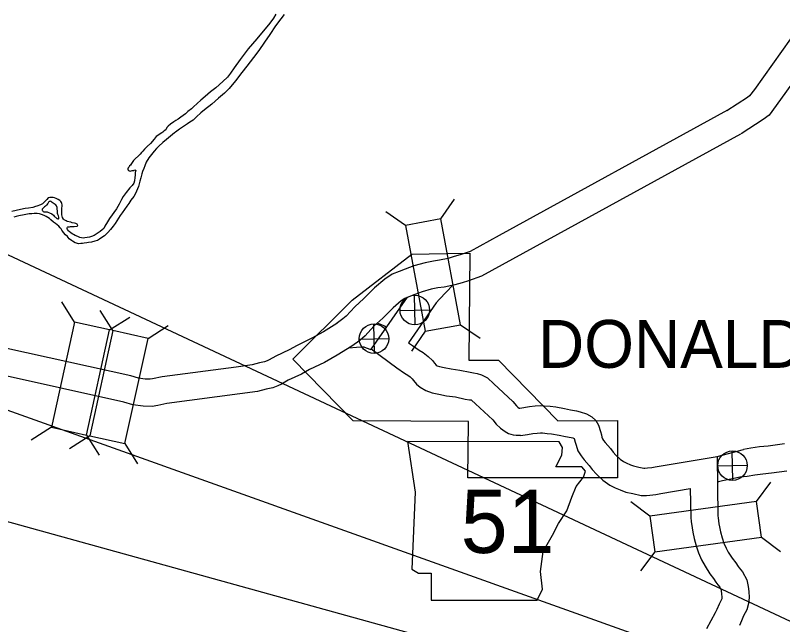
# Model space of a CAD drawing. Extents: x 1373862 to 1377080, y 1164775 to 1170415.
# Drawn here: x 1374487.3 to 1374572, y 1170030.2 to 1170097.4 of the extents above; entities that cross this region are included whole.
import ezdxf

# ---------------------------------------------------------------- set-up
doc = ezdxf.new("R2010")
doc.units = 0
doc.layers.add('1', color=7, linetype='Continuous')
doc.layers.add('Default', color=7, linetype='Continuous')

msp = doc.modelspace()

# ---------------------------------------------------------------- linework, layer by layer
at = {"layer": '1'}
for p in [(1374155.089, 1170226.036), (1374172.843, 1170165.768), (1374199.554, 1170121.066)]:
    msp.add_line(p, (1374640.758, 1169998.763), dxfattribs=at)
at = {"layer": 'Default'}
for p, q in [((1374534.295, 1170074.917), (1374535.789, 1170077.093)), ((1374530.401, 1170074.194), (1374528.225, 1170075.688)), ((1374531.457, 1170063.225), (1374531.382, 1170066.48)), ((1374493.871, 1170063.524), (1374492.452, 1170065.75)), ((1374498.109, 1170062.586), (1374496.689, 1170064.812)), ((1374529.793, 1170064.815), (1374533.047, 1170064.89)), ((1374497.738, 1170062.668), (1374499.964, 1170064.088)), ((1374526.958, 1170060.066), (1374526.883, 1170063.321)), ((1374501.975, 1170061.731), (1374504.201, 1170063.151)), ((1374532.57, 1170062.514), (1374531.076, 1170060.337)), ((1374536.464, 1170063.237), (1374538.64, 1170061.742)), ((1374525.293, 1170061.656), (1374528.548, 1170061.731)), ((1374491.306, 1170051.924), (1374489.08, 1170050.504)), ((1374495.543, 1170050.987), (1374493.317, 1170049.567)), ((1374495.172, 1170051.069), (1374496.592, 1170048.843)), ((1374499.41, 1170050.131), (1374500.829, 1170047.906)), ((1374566.521, 1170046.074), (1374566.446, 1170049.329)), ((1374564.856, 1170047.664), (1374568.111, 1170047.739)), ((1374569.134, 1170043.75), (1374570.726, 1170045.857)), ((1374557.368, 1170042.113), (1374555.262, 1170043.705)), ((1374569.68, 1170039.828), (1374571.786, 1170038.237)), ((1374557.914, 1170038.191), (1374556.322, 1170036.085))]:
    msp.add_line(p, q, dxfattribs=at)
for points in [[(1374516.087, 1170097.466), (1374515.821, 1170097.033), (1374515.406, 1170096.479), (1374513.983, 1170094.764), (1374513.043, 1170093.675), (1374512.134, 1170092.475), (1374511.503, 1170091.558), (1374511.069, 1170090.964), (1374510.743, 1170090.52), (1374510.247, 1170090.075), (1374509.464, 1170089.368), (1374508.869, 1170088.932), (1374508.284, 1170088.416), (1374507.818, 1170087.992), (1374506.996, 1170087.254), (1374506.758, 1170087.031), (1374506.361, 1170086.737), (1374506.123, 1170086.505), (1374505.865, 1170086.303), (1374505.597, 1170086.13), (1374505.309, 1170085.917), (1374505.031, 1170085.755), (1374504.833, 1170085.623), (1374504.445, 1170085.359), (1374504.208, 1170085.137), (1374504.069, 1170084.985), (1374503.931, 1170084.744), (1374503.773, 1170084.632), (1374503.604, 1170084.481), (1374503.495, 1170084.4)], [(1374516.996, 1170097.454), (1374516.62, 1170096.98), (1374516.058, 1170096.184), (1374515.406, 1170095.247), (1374514.834, 1170094.401), (1374514.203, 1170093.474), (1374513.62, 1170092.708), (1374512.889, 1170091.75), (1374512.326, 1170091.045), (1374511.644, 1170090.137), (1374510.933, 1170089.3), (1374510.428, 1170088.785), (1374509.753, 1170088.219), (1374509.03, 1170087.551), (1374508.196, 1170086.933), (1374507.8, 1170086.62), (1374507.314, 1170086.165), (1374506.948, 1170085.811), (1374506.6, 1170085.558), (1374506.352, 1170085.375), (1374505.766, 1170085.01), (1374505.458, 1170084.797), (1374505.141, 1170084.584), (1374504.992, 1170084.472), (1374504.913, 1170084.402)], [(1374573.9, 1170096.142), (1374568.908, 1170089.177), (1374568.375, 1170088.479), (1374568.147, 1170088.299), (1374565.848, 1170086.837)], [(1374576.338, 1170094.394), (1374571.32, 1170087.393), (1374570.53, 1170086.357), (1374569.885, 1170085.849), (1374567.457, 1170084.305)], [(1374565.932, 1170086.887), (1374540.744, 1170073.094), (1374537.549, 1170071.328)], [(1374504.913, 1170084.402), (1374504.01, 1170083.677), (1374503.617, 1170083.348), (1374503.166, 1170082.919), (1374502.912, 1170082.654), (1374502.658, 1170082.358), (1374502.356, 1170082.002), (1374502.083, 1170081.656), (1374501.774, 1170081.149), (1374501.622, 1170080.766), (1374501.499, 1170080.453), (1374501.385, 1170080.141), (1374501.301, 1170079.859), (1374501.17, 1170079.435), (1374501.068, 1170079.053), (1374501.013, 1170078.772), (1374500.929, 1170078.48), (1374500.815, 1170078.207), (1374500.585, 1170077.712), (1374500.393, 1170077.368), (1374500.081, 1170076.961), (1374499.849, 1170076.596), (1374499.645, 1170076.302), (1374499.363, 1170075.936), (1374499.111, 1170075.58), (1374498.907, 1170075.296), (1374498.703, 1170075.001), (1374498.366, 1170074.394), (1374498.142, 1170074.089), (1374497.84, 1170073.743), (1374497.537, 1170073.406), (1374497.371, 1170073.223), (1374497.175, 1170073.039), (1374496.88, 1170072.843), (1374496.624, 1170072.657), (1374496.387, 1170072.533), (1374496.089, 1170072.447), (1374495.751, 1170072.35), (1374495.423, 1170072.303), (1374495.214, 1170072.269), (1374494.945, 1170072.234), (1374494.756, 1170072.21), (1374494.567, 1170072.176), (1374494.347, 1170072.172), (1374493.926, 1170072.283), (1374493.643, 1170072.448), (1374493.542, 1170072.506), (1374493.288, 1170072.701), (1374493.155, 1170072.869), (1374493.074, 1170072.957), (1374492.86, 1170073.163), (1374492.656, 1170073.389), (1374492.573, 1170073.508), (1374492.47, 1170073.666), (1374492.388, 1170073.794), (1374492.265, 1170073.932), (1374492.122, 1170074.089), (1374491.94, 1170074.246), (1374491.767, 1170074.393), (1374491.544, 1170074.548), (1374491.249, 1170074.813), (1374491.087, 1170074.95), (1374490.925, 1170075.057), (1374490.733, 1170075.173), (1374490.501, 1170075.288), (1374490.209, 1170075.403), (1374489.998, 1170075.459), (1374489.748, 1170075.494), (1374489.398, 1170075.507), (1374489.169, 1170075.482), (1374488.86, 1170075.466), (1374488.323, 1170075.365), (1374487.706, 1170075.253), (1374487.418, 1170075.177), (1374487.151, 1170075.081)], [(1374503.495, 1170084.4), (1374502.885, 1170083.995), (1374502.642, 1170083.689), (1374502.251, 1170083.231), (1374501.899, 1170082.874), (1374501.605, 1170082.598), (1374501.41, 1170082.373), (1374501.254, 1170082.21), (1374501.117, 1170082.037), (1374500.95, 1170081.904), (1374500.509, 1170081.495), (1374500.373, 1170081.342), (1374500.237, 1170081.139), (1374500.159, 1170081.027), (1374500.033, 1170080.844), (1374499.945, 1170080.743), (1374499.887, 1170080.651), (1374499.8, 1170080.549), (1374499.762, 1170080.439), (1374499.764, 1170080.348), (1374499.774, 1170080.319), (1374499.795, 1170080.279), (1374499.836, 1170080.24), (1374499.896, 1170080.201), (1374499.946, 1170080.192), (1374500.007, 1170080.183), (1374500.116, 1170080.205), (1374500.225, 1170080.238), (1374500.295, 1170080.249), (1374500.394, 1170080.261), (1374500.464, 1170080.282), (1374500.513, 1170080.303), (1374500.584, 1170080.275), (1374500.615, 1170080.235), (1374500.569, 1170080.014), (1374500.555, 1170079.744), (1374500.53, 1170079.473), (1374500.498, 1170079.092), (1374500.393, 1170078.829), (1374500.218, 1170078.586), (1374499.964, 1170078.32), (1374499.565, 1170077.802), (1374499.235, 1170077.365), (1374499.062, 1170077.031), (1374498.802, 1170076.545), (1374498.483, 1170075.998), (1374497.716, 1170074.932), (1374497.494, 1170074.567), (1374497.204, 1170074.101), (1374497.099, 1170073.858), (1374496.912, 1170073.694), (1374496.696, 1170073.53), (1374496.49, 1170073.376), (1374496.026, 1170073.086), (1374495.729, 1170072.95), (1374495.521, 1170072.906), (1374495.013, 1170072.816), (1374494.815, 1170072.772), (1374494.624, 1170072.818), (1374494.463, 1170072.855), (1374494.212, 1170072.97), (1374493.919, 1170073.094), (1374493.758, 1170073.171), (1374493.587, 1170073.268), (1374493.465, 1170073.365), (1374493.282, 1170073.502), (1374493.2, 1170073.6), (1374493.078, 1170073.748), (1374493.036, 1170073.847), (1374493.044, 1170073.918), (1374493.073, 1170073.988), (1374493.132, 1170074.019), (1374493.302, 1170074.033), (1374493.421, 1170074.065), (1374493.56, 1170074.078), (1374493.7, 1170074.071), (1374493.83, 1170074.063), (1374494.168, 1170074.12), (1374494.158, 1170074.12), (1374494.227, 1170074.161), (1374494.206, 1170074.251), (1374494.164, 1170074.32), (1374493.993, 1170074.417), (1374493.862, 1170074.454), (1374493.612, 1170074.489), (1374493.441, 1170074.536), (1374493.05, 1170074.628), (1374492.929, 1170074.696), (1374492.727, 1170074.812), (1374492.646, 1170074.871), (1374492.532, 1170075.059), (1374492.457, 1170075.337), (1374492.463, 1170075.538), (1374492.46, 1170075.668), (1374492.467, 1170075.828), (1374492.472, 1170076.048), (1374492.481, 1170076.139), (1374492.498, 1170076.279), (1374492.516, 1170076.38), (1374492.504, 1170076.47), (1374492.471, 1170076.609)], [(1374503.495, 1170084.4), (1374503.396, 1170084.309)], [(1374567.373, 1170084.256), (1374542.19, 1170070.465), (1374538.771, 1170068.576)], [(1374492.471, 1170076.609), (1374492.439, 1170076.709), (1374492.347, 1170076.837), (1374492.225, 1170076.945), (1374492.053, 1170077.041), (1374491.841, 1170077.167), (1374491.65, 1170077.233), (1374491.5, 1170077.25), (1374491.25, 1170077.275), (1374491.15, 1170077.274), (1374490.971, 1170077.22), (1374490.805, 1170077.036), (1374490.639, 1170076.853), (1374490.473, 1170076.699), (1374490.315, 1170076.576), (1374490.108, 1170076.442), (1374489.702, 1170076.304), (1374489.553, 1170076.261), (1374489.246, 1170076.154), (1374488.797, 1170076.095), (1374488.399, 1170076.047), (1374487.892, 1170075.927), (1374487.415, 1170075.828), (1374486.938, 1170075.738)], [(1374491.734, 1170076.504), (1374491.492, 1170076.65), (1374491.401, 1170076.708), (1374491.37, 1170076.757), (1374491.269, 1170076.825), (1374491.188, 1170076.854), (1374491.129, 1170076.843), (1374491.069, 1170076.811), (1374491.001, 1170076.74), (1374490.914, 1170076.598), (1374490.778, 1170076.425), (1374490.66, 1170076.303), (1374490.562, 1170076.221), (1374490.463, 1170076.159), (1374490.415, 1170076.078), (1374490.326, 1170076.026), (1374490.287, 1170075.975), (1374490.298, 1170075.925), (1374490.309, 1170075.875), (1374490.331, 1170075.816), (1374490.362, 1170075.756), (1374490.422, 1170075.727), (1374490.493, 1170075.699), (1374490.493, 1170075.689), (1374490.583, 1170075.68), (1374490.643, 1170075.682), (1374490.712, 1170075.693), (1374490.833, 1170075.675), (1374490.923, 1170075.647), (1374491.114, 1170075.581), (1374491.356, 1170075.476)], [(1374491.356, 1170075.476), (1374491.539, 1170075.319), (1374491.63, 1170075.221), (1374491.702, 1170075.152), (1374491.753, 1170075.103), (1374491.844, 1170075.025), (1374491.915, 1170074.966), (1374491.956, 1170074.937), (1374492.016, 1170074.918), (1374492.086, 1170074.93), (1374492.115, 1170074.94), (1374492.134, 1170075.001), (1374492.122, 1170075.11), (1374492.109, 1170075.24), (1374492.026, 1170075.399), (1374491.994, 1170075.508), (1374491.991, 1170075.668), (1374491.978, 1170075.818), (1374491.966, 1170075.898), (1374491.953, 1170076.058), (1374491.931, 1170076.158), (1374491.898, 1170076.287), (1374491.877, 1170076.357), (1374491.795, 1170076.465), (1374491.734, 1170076.504)], [(1374537.334, 1170052.582), (1374524.619, 1170052.656), (1374517.967, 1170059.433), (1374524.517, 1170065.945), (1374531.077, 1170071.016)], [(1374537.549, 1170071.328), (1374536.433, 1170070.945), (1374535.779, 1170070.75), (1374535.108, 1170070.551), (1374534.155, 1170070.344), (1374533.501, 1170070.254), (1374532.556, 1170070.078), (1374531.303, 1170069.729), (1374530.356, 1170069.366), (1374529.687, 1170069.111), (1374528.94, 1170068.819), (1374528.12, 1170068.278), (1374526.988, 1170067.314), (1374525.813, 1170066.118), (1374524.794, 1170065.211), (1374523.847, 1170064.182), (1374523.479, 1170063.869), (1374522.748, 1170063.336)], [(1374531.077, 1170071.016), (1374534.908, 1170071.087), (1374537.482, 1170071.121), (1374537.388, 1170059.32), (1374540.642, 1170059.333), (1374547.212, 1170052.642), (1374553.813, 1170052.682), (1374553.784, 1170046.347), (1374537.284, 1170046.345), (1374537.333, 1170052.449)], [(1374538.771, 1170068.576), (1374537.348, 1170068.087), (1374536.633, 1170067.874), (1374535.854, 1170067.644), (1374534.68, 1170067.388), (1374533.98, 1170067.291), (1374533.234, 1170067.153), (1374532.244, 1170066.877), (1374531.428, 1170066.564), (1374530.768, 1170066.312), (1374530.327, 1170066.14), (1374529.925, 1170065.875), (1374529.035, 1170065.117), (1374527.882, 1170063.944), (1374526.9, 1170063.069), (1374525.932, 1170062.017), (1374525.338, 1170061.511), (1374524.476, 1170060.883)], [(1374535.627, 1170067.612), (1374534.137, 1170066.058), (1374533.786, 1170065.649), (1374530.738, 1170061.245), (1374531.162, 1170060.931), (1374531.895, 1170060.441), (1374532.358, 1170060.17), (1374532.893, 1170059.751), (1374533.371, 1170059.277), (1374533.587, 1170059.008), (1374533.778, 1170058.782), (1374533.78, 1170058.78), (1374533.908, 1170058.706), (1374534.144, 1170058.62), (1374534.655, 1170058.522), (1374535.424, 1170058.357), (1374536.4, 1170058.227), (1374537.53, 1170057.993), (1374537.9, 1170057.93), (1374538.32, 1170057.873), (1374538.793, 1170057.725), (1374539.441, 1170057.371), (1374540.154, 1170056.708), (1374542.256, 1170054.785), (1374542.637, 1170054.297), (1374542.8, 1170054.14), (1374542.925, 1170054.053), (1374543.027, 1170054.048)], [(1374530.578, 1170066.286), (1374526.617, 1170060.561), (1374529.436, 1170058.477), (1374530.302, 1170057.897), (1374530.667, 1170057.684), (1374530.904, 1170057.498), (1374531.138, 1170057.266), (1374531.271, 1170057.101), (1374531.611, 1170056.697), (1374531.996, 1170056.346), (1374532.636, 1170055.975), (1374533.345, 1170055.719), (1374534.057, 1170055.582), (1374534.911, 1170055.399), (1374535.898, 1170055.267), (1374536.974, 1170055.045), (1374537.445, 1170054.964), (1374537.637, 1170054.938), (1374537.673, 1170054.918), (1374538.12, 1170054.503), (1374540.045, 1170052.742), (1374540.402, 1170052.284), (1374540.891, 1170051.813), (1374541.402, 1170051.458), (1374541.782, 1170051.236), (1374542.28, 1170051.081), (1374542.619, 1170051.065), (1374543.084, 1170051.041)], [(1374522.827, 1170063.39), (1374521.336, 1170062.442), (1374520.071, 1170061.737), (1374518.443, 1170060.956), (1374517.562, 1170060.472), (1374516.076, 1170059.78), (1374515.347, 1170059.376), (1374515.113, 1170059.268), (1374514.837, 1170059.156), (1374514.29, 1170059.026), (1374513.464, 1170058.816), (1374511.72, 1170058.571), (1374503.538, 1170057.492), (1374502.479, 1170057.274), (1374502.216, 1170057.227), (1374501.678, 1170057.244), (1374500.934, 1170057.331), (1374500.092, 1170057.6), (1374486.398, 1170060.629)], [(1374528.27, 1170062.95), (1374528.088, 1170063.081), (1374527.677, 1170063.268), (1374527.278, 1170063.406)], [(1374524.476, 1170060.883), (1374522.871, 1170059.863), (1374521.451, 1170059.072), (1374519.816, 1170058.287), (1374518.919, 1170057.794), (1374517.438, 1170057.105), (1374516.706, 1170056.699), (1374516.307, 1170056.515), (1374515.751, 1170056.29), (1374515.006, 1170056.113), (1374514.044, 1170055.868), (1374512.124, 1170055.599), (1374504.037, 1170054.532), (1374503.047, 1170054.328), (1374502.435, 1170054.218), (1374501.454, 1170054.25), (1374500.297, 1170054.385), (1374499.31, 1170054.701), (1374485.769, 1170057.696)], [(1374526.484, 1170060.506), (1374526.206, 1170060.603), (1374525.893, 1170060.732), (1374525.834, 1170060.745), (1374525.546, 1170060.751), (1374524.986, 1170060.731), (1374524.124, 1170060.66)], [(1374526.484, 1170060.506), (1374526.617, 1170060.561)], [(1374543.027, 1170054.043), (1374544.076, 1170054.234), (1374544.722, 1170054.282), (1374545.267, 1170054.317), (1374545.696, 1170054.298), (1374546.348, 1170054.245), (1374546.978, 1170054.166), (1374547.936, 1170053.983), (1374548.595, 1170053.849), (1374549.285, 1170053.729), (1374549.691, 1170053.635), (1374550.367, 1170053.394), (1374550.974, 1170053.086), (1374551.405, 1170052.67), (1374551.714, 1170052.167), (1374551.916, 1170051.473), (1374552.014, 1170051.092), (1374552.083, 1170050.852), (1374552.151, 1170050.656), (1374552.26, 1170050.483), (1374552.448, 1170050.238), (1374553.017, 1170049.58), (1374553.311, 1170049.184), (1374553.621, 1170048.848), (1374554.087, 1170048.407), (1374554.443, 1170048.144), (1374554.763, 1170048.005), (1374555.232, 1170047.791), (1374555.565, 1170047.666), (1374556.135, 1170047.542), (1374556.704, 1170047.415), (1374556.799, 1170047.417), (1374557.121, 1170047.451), (1374557.577, 1170047.476), (1374557.953, 1170047.574), (1374564.791, 1170048.715)], [(1374537.333, 1170052.449), (1374537.334, 1170052.582)], [(1374543.088, 1170051.016), (1374543.848, 1170051.143), (1374544.457, 1170051.254), (1374544.927, 1170051.289), (1374545.299, 1170051.313), (1374545.51, 1170051.304), (1374546.038, 1170051.26), (1374546.509, 1170051.201), (1374547.355, 1170051.04), (1374548.039, 1170050.901), (1374548.692, 1170050.787), (1374548.847, 1170050.751), (1374549.02, 1170050.689), (1374549.023, 1170050.679), (1374549.12, 1170050.303), (1374549.222, 1170049.946), (1374549.43, 1170049.347), (1374549.795, 1170048.768), (1374550.12, 1170048.343), (1374550.676, 1170047.701), (1374550.997, 1170047.269), (1374551.484, 1170046.74), (1374552.158, 1170046.102), (1374552.936, 1170045.527), (1374553.543, 1170045.264), (1374554.082, 1170045.018), (1374554.715, 1170044.781), (1374555.488, 1170044.612), (1374556.403, 1170044.408), (1374556.987, 1170044.42), (1374557.362, 1170044.46), (1374558.043, 1170044.497), (1374558.58, 1170044.637), (1374561.833, 1170045.18)], [(1374572.235, 1170050.086), (1374570.442, 1170049.845), (1374569.463, 1170049.755), (1374568.502, 1170049.609), (1374567.703, 1170049.485)], [(1374564.791, 1170048.715), (1374567.703, 1170049.485)], [(1374564.791, 1170048.715), (1374564.869, 1170042.155), (1374564.894, 1170041.932), (1374564.993, 1170041.294), (1374565.043, 1170040.939), (1374565.176, 1170040.399), (1374565.341, 1170039.738), (1374565.548, 1170039.164), (1374565.774, 1170038.613), (1374566.027, 1170038.161), (1374566.469, 1170037.48), (1374566.84, 1170036.978), (1374567.112, 1170036.577), (1374567.226, 1170036.42), (1374567.59, 1170035.997), (1374568.06, 1170035.116), (1374568.217, 1170034.359), (1374568.278, 1170033.82), (1374568.317, 1170033.16), (1374568.266, 1170032.481), (1374568.067, 1170031.803), (1374567.717, 1170031.135), (1374567.484, 1170030.594), (1374567.245, 1170030.079)], [(1374572.492, 1170047.093), (1374570.78, 1170046.863), (1374569.826, 1170046.775), (1374568.956, 1170046.644), (1374568.122, 1170046.515), (1374567.305, 1170046.41), (1374566.814, 1170046.321), (1374565.935, 1170046.128), (1374565.382, 1170046.008), (1374564.925, 1170045.905), (1374564.824, 1170045.872)], [(1374561.833, 1170045.18), (1374561.871, 1170041.971), (1374561.919, 1170041.535), (1374562.026, 1170040.855), (1374562.093, 1170040.372), (1374562.264, 1170039.676), (1374562.468, 1170038.864), (1374562.748, 1170038.086), (1374563.067, 1170037.306), (1374563.457, 1170036.61), (1374564.003, 1170035.769), (1374564.392, 1170035.244), (1374564.655, 1170034.856), (1374564.87, 1170034.559), (1374565.099, 1170034.292), (1374565.21, 1170034.084), (1374565.252, 1170033.884), (1374565.288, 1170033.564), (1374565.31, 1170033.184), (1374565.298, 1170033.021), (1374565.272, 1170032.933), (1374565.007, 1170032.427), (1374564.744, 1170031.817), (1374564.581, 1170031.464), (1374564.079, 1170030.599), (1374563.636, 1170029.699)]]:
    msp.add_lwpolyline(points, dxfattribs=at)
for points in [[(1374536.464, 1170063.237), (1374534.295, 1170074.917), (1374530.401, 1170074.194), (1374532.57, 1170062.514)], [(1374493.871, 1170063.524), (1374491.306, 1170051.924), (1374495.172, 1170051.069), (1374497.738, 1170062.668)], [(1374498.109, 1170062.586), (1374495.543, 1170050.987), (1374499.41, 1170050.131), (1374501.975, 1170061.731)], [(1374530.611, 1170050.344), (1374531.449, 1170044.761), (1374531.077, 1170036.293), (1374531.821, 1170035.828), (1374533.217, 1170035.828), (1374533.217, 1170032.851), (1374544.941, 1170032.851), (1374545.499, 1170034.06), (1374545.313, 1170036.014), (1374545.592, 1170038.247), (1374546.616, 1170040.015), (1374547.267, 1170041.318), (1374548.198, 1170042.714), (1374548.756, 1170044.203), (1374549.221, 1170045.412), (1374550.059, 1170046.436), (1374550.245, 1170047.087), (1374549.872, 1170047.552), (1374546.988, 1170047.552), (1374547.639, 1170048.855), (1374547.732, 1170049.692), (1374547.346, 1170050.336)], [(1374557.914, 1170038.191), (1374569.68, 1170039.828), (1374569.134, 1170043.75), (1374557.368, 1170042.113)]]:
    msp.add_lwpolyline(points, close=True, dxfattribs=at)
for centre in [(1374531.42, 1170064.852), (1374526.921, 1170061.694), (1374566.484, 1170047.701)]:
    msp.add_circle(centre, 1.628, dxfattribs=at)

# ---------------------------------------------------------------- texts
for s, height, p in [('DONALDSON', 5.28, (1374545.018, 1170058.481)), ('51', 6.9696, (1374536.487, 1170038.067))]:
    msp.add_text(s, height=height, dxfattribs=at).set_placement(p)

doc.saveas('drawing.dxf')
